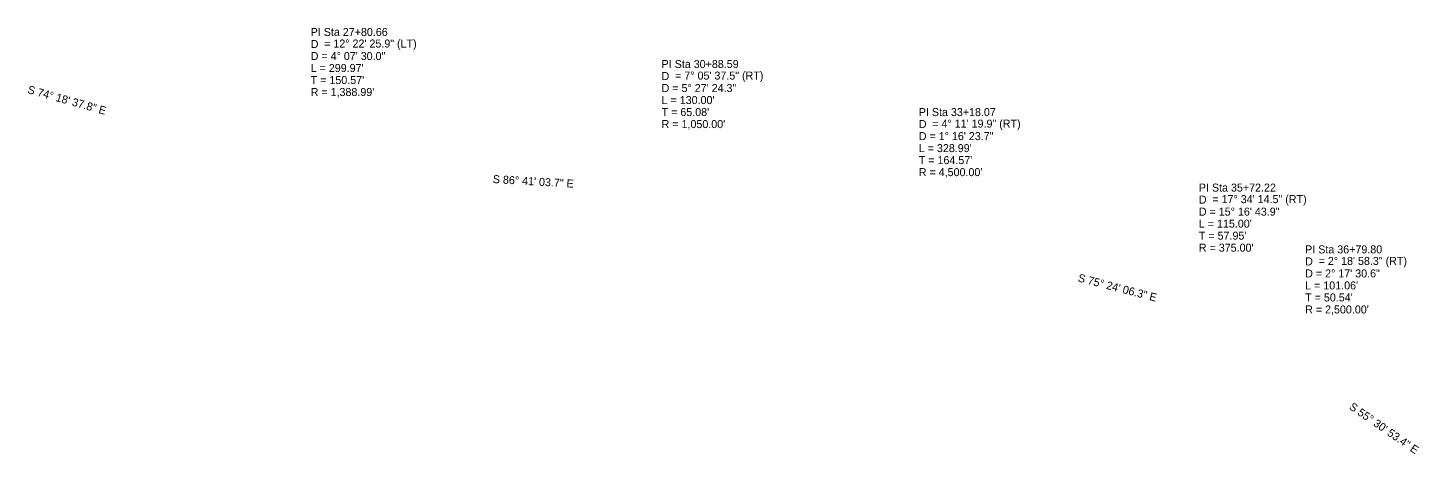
# Model space of a CAD drawing. Extents: x 928111 to 937215, y 684185 to 686530.
# Drawn here: x 929365 to 930582, y 685523 to 685895 of the extents above; entities that cross this region are included whole.
import ezdxf

# ---------------------------------------------------------------- set-up
doc = ezdxf.new("R2010")
doc.units = 0
doc.layers.add('Exist Horizontal Alignment Curve and Spiral Data', color=7, linetype='Continuous')
doc.layers.add('Exist Horizontal Alignment Direction Label', color=7, linetype='Continuous')

msp = doc.modelspace()

# ---------------------------------------------------------------- texts
at = {"layer": 'Exist Horizontal Alignment Curve and Spiral Data'}
for s, p in [('PI Sta 27+80.66', (929612, 685888)), ('D', (929612, 685877.5)), ('D = 4%%d 07\' 30.0"', (929612, 685867)), ('= 12%%d 22\' 25.9" (LT)', (929623.8, 685877.9)), ("L = 299.97'", (929612, 685856.5)), ('PI Sta 30+88.59', (929919, 685860)), ("T = 150.57'", (929612, 685846)), ('D', (929919, 685849.5)), ('= 7%%d 05\' 37.5" (RT)', (929930.8, 685849.9)), ("R = 1,388.99'", (929612, 685835.5)), ('D = 5%%d 27\' 24.3"', (929919, 685839)), ("T = 65.08'", (929919, 685818)), ("L = 130.00'", (929919, 685828.5)), ('PI Sta 33+18.07', (930144, 685818)), ("R = 1,050.00'", (929919, 685807.5)), ('D', (930144, 685807.5)), ('= 4%%d 11\' 19.9" (RT)', (930155.8, 685807.9)), ('D = 1%%d 16\' 23.7"', (930144, 685797)), ("L = 328.99'", (930144, 685786.5)), ("T = 164.57'", (930144, 685776)), ("R = 4,500.00'", (930144, 685765.5)), ('PI Sta 35+72.22', (930389, 685752)), ('D', (930389, 685741.5)), ('= 17%%d 34\' 14.5" (RT)', (930400.8, 685741.9)), ('D = 15%%d 16\' 43.9"', (930389, 685731)), ("L = 115.00'", (930389, 685720.5)), ("T = 57.95'", (930389, 685710)), ("R = 375.00'", (930389, 685699.5)), ('PI Sta 36+79.80', (930482, 685698)), ('D', (930482, 685687.5)), ('= 2%%d 18\' 58.3" (RT)', (930493.8, 685687.9)), ('D = 2%%d 17\' 30.6"', (930482, 685677)), ("L = 101.06'", (930482, 685666.5)), ("T = 50.54'", (930482, 685656)), ("R = 2,500.00'", (930482, 685645.5))]:
    msp.add_text(s, height=7, dxfattribs=at).set_placement(p)
at = {"layer": 'Exist Horizontal Alignment Direction Label'}
for s, rotation, p in [('S 74%%d 18\' 37.8" E', 344.3105, (929363.8, 685838.2)), ('S 86%%d 41\' 03.7" E', 356.6844, (929771.2, 685759.5)), ('S 75%%d 24\' 06.3" E', 345.4017, (930282.7, 685673.6)), ('S 55%%d 30\' 53.4" E', 325.5148, (930519.9, 685562.4))]:
    msp.add_text(s, height=7, rotation=rotation, dxfattribs=at).set_placement(p)

doc.saveas('drawing.dxf')
